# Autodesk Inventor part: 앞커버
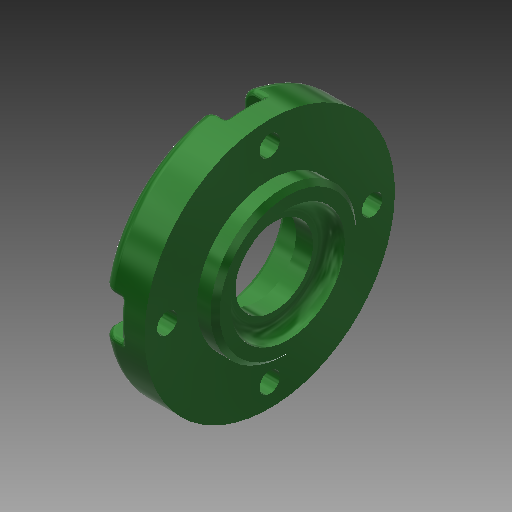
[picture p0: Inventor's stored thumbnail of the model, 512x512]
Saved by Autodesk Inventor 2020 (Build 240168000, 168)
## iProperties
Created: 2015-11
Part Number: 앞커버
Material: 알루미늄 6061
Document SubType Name: Modeling
Designer: mduedu
Density: 1 g/cm^3
Appearance: 매끄러움 - 짙은 산림 녹색
Author: mduedu
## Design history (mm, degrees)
sketch "스케치1"
  geometry: L1 (-7, 0)-(7, 0); L2 (-7, 0)-(-7, 27.5); L3 (-7, 27.5)-(3, 27.5); L4 (3, 27.5)-(3, 16); L5 (3, 16)-(7, 16); L6 (7, 16)-(7, 0); 2 further points
  constraints: 12 end point, 3 perpendicular, 2 parallel, 1 coincident, 1 horizontal, 1 midpoint
  dimensions: "d0" = 14 distance of L1.start L1.end; "d1" = 55 diameter of L3 L1; "d2" = 4 distance of L4.end L5.end; "d3" = 32 diameter of L5 L1
revolve "회전1" sketch "스케치1" stored, may be unused: angle "d4" = 90 deg
hole "구멍1" diameter "d7" = 25; stored, may be unused: countersink angle "d11" = 90 deg, drill point angle "d13" = 0 deg; dims "d5" = 10, "d6" = 10, "d8" = 6, "d9" = 4, "d10" = 2, "d12" = 3
hole "구멍2" diameter "d16" = 25; stored, may be unused: countersink angle "d20" = 90 deg, drill point angle "d22" = 0 deg; dims "d17" = 6, "d18" = 4, "d19" = 2, "d21" = 7.3, "d61" = 10, "d62" = 10
hole "구멍3" diameter "d25" = 17; stored, may be unused: countersink angle "d29" = 90 deg, drill point angle "d31" = 0 deg; dims "d23" = 10, "d24" = 10, "d26" = 6, "d27" = 4, "d28" = 2, "d30" = 4.2
chamfer "모따기1" distance "d32" = 0.7; stored, may be unused: second distance "d33" = 2, angle "d34" = 30 deg
fillet "모깎기1" dims "d35" = 0.3
fillet "모깎기2" dims "d36" = 3
fillet "모깎기3" dims "d37" = 3
sketch "스케치2" dims "d39" = 45
  geometry: C1 r 12.904 at (0, 0) reference; C2 r 24.5 at (0, 0) reference; 6 further points
  constraints: 2 vertical alignment, 1 coincident, 7 other
  dimensions: "d42" = 360 deg dimension on point (0, 0) point (0, 22.5) (derived)
sketch "스케치3"
  geometry: 8 further points
  constraints: 4 coincident
hole "구멍4" sketch "스케치3" at (-22.5, 0), (0, -22.5), (22.5, 0), (0, 22.5) diameter "d44" = 4.5; stored, may be unused: countersink angle "d48" = 90 deg, drill point angle "d50" = 0 deg; dims "d45" = 6, "d46" = 8, "d47" = 4.6, "d49" = 8
sketch "스케치4"
  geometry: L1 (-4, 0)-(-4, -4.708); L2 (4, 0)-(4, -4.708); A1 r 4 centre (0, 0) between (-4, 0) and (4, 0) reference; A2 r 27.5 centre (0, 22.5) between (-4, -4.708) and (4, -4.708) reference; 3 further points
  constraints: 4 end point, 4 point on circle, 2 tangent, 1 parallel, 1 vertical
extrude "돌출1" cut sketch "스케치4" extent not by distance; stored distance "d51" = 0; taper "d52" = 0 deg
fillet "모깎기5" dims "d56" = 0.3
fillet "모깎기6" dims "d57" = 1
chamfer "모따기2" distance "d63" = 1; stored, may be unused: second distance "d64" = 2, angle "d65" = 45 deg
node "솔리드1"
pattern_circular "원형 패턴1" dims angle "d54" = 360 deg
